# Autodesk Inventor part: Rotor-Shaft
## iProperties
Shininess: 64.0
Length Units: 11269
Angle Units: 11279
Time Units: 11290
Mass Units: 11283
Length Display Precision: 3
Angle Display Precision: 2
Compacted: True
Part Number: Rotor-Shaft
Document SubType Name: Modeling
Created: 2004-01
Designer: Administrator
Manufacturer: Standard
Standards Organization: Custom
Density: 1 g/cm^3
Density: 0.0
Volumn: 0.0
Area: 0.0
PropertySet Name: Model Information
Control State: 0
Master: False
Checked Out: False
Author: Administrator
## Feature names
1. Extrusion1
2. Extrusion2
3. Chamfer1
